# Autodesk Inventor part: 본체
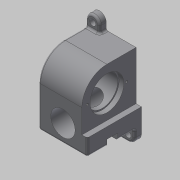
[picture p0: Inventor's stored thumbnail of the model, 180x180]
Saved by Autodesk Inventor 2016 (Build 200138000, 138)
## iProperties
Created: 2019-06
Part Number: 본체
Material: 일반
Document SubType Name: Modeling
Designer: mduedu
Density: 1 g/cm^3
Appearance: 기본값
Author: mduedu
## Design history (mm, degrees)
sketch "스케치1"
  geometry: L1 (37, 0)-(37, -43); L2 (37, -43)-(-60, -43); L3 (-60, -43)-(-60, 37); L4 (-60, 37)-(0, 37); A1 r 37 centre (0, 0) between (37, 0) and (0, 37); 1 further point
  constraints: 8 end point, 2 point on circle, 2 tangent, 1 centre point, 1 coincident, 1 horizontal, 1 parallel, 1 perpendicular, 1 vertical
  dimensions: "d0" = 37 radius of A1; "d2" = 80 distance of L2.end L3.end; "d3" = 97 distance of L1.end L2.end
extrude "돌출1" new body sketch "스케치1" stored distance "d4" = 72; taper "d5" = 0 deg
sketch "스케치2"
  geometry: L1 (72, 25)-(64, 25); L2 (64, 25)-(64, 97); L3 (64, 97)-(72, 97); L4 (72, 97)-(72, 25); L5 (72, 97)-(0, 97) reference; L6 (72, 60)-(72, 0) reference; 1 further point
  constraints: 8 end point, 2 collinear, 2 parallel, 1 horizontal, 1 perpendicular
  dimensions: "d6" = 72 distance between parallel lines of L1 L3; "d8" = 8 distance of L1.start L1.end
extrude "돌출2" cut sketch "스케치2" stored distance "d9" = 72; taper "d10" = 0 deg
sketch "스케치3"
  geometry: L1 (-36, -60)-(-36, 37) reference; L2 (-36, 37)-(28, 37) reference; L3 (28, 37)-(28, -35) reference; L4 (28, -35)-(36, -35) reference; L5 (36, -35)-(36, -60) reference; L6 (36, -60)-(-36, -60) reference; L7 (-36, 0)-(-19, 0); L8 (-19, 0)-(-19, 17.5); L9 (-19, 17.5)-(-36, 17.5); L10 (-36, 17.5)-(-36, 0); L11 (-19, 0)-(21, 0); L12 (21, 0)-(21, 23); L13 (21, 23)-(-19, 23); L14 (-19, 23)-(-19, 0); L15 (21, 0)-(28, 0); L16 (28, 0)-(28, 25); L17 (28, 25)-(21, 25); L18 (21, 25)-(21, 0); 1 further point
  constraints: 24 end point, 6 parallel, 3 horizontal, 3 perpendicular, 2 point on line, 1 horizontal alignment
  dimensions: "d11" = 7 distance of L16.end L17.end; "d13" = 47 distance between parallel lines of L3 L8; "d14" = 50 diameter of L17 L15; "d15" = 46 diameter of L13 L11; "d16" = 35 diameter of L9 L7
revolve "회전1" sketch "스케치3" stored, may be unused: angle "d17" = 90 deg
sketch "스케치4"
  geometry: C1 r 28 at (0, 0); 1 further point
  constraints: 1 centre point, 1 coincident
  dimensions: "d18" = 56 diameter of C1
extrude "돌출3" cut sketch "스케치4" distance "d19" = 2; taper "d20" = 0 deg
fillet "모깎기1" dims "d21" = 3
sketch "스케치5"
  geometry: C1 r 18 at (36, 26); 1 further point
  constraints: 1 centre point, 1 vertical alignment
  dimensions: "d22" = 36 diameter of C1; "d23" = 34 distance of C1.centre point (36, 60)
extrude "돌출4" cut sketch "스케치5" stored distance "d24" = 2; taper "d25" = 0 deg
sketch "스케치6"
  geometry: L1 (-37, -60)-(43, -60) reference; L2 (-8, -60)-(8, -60); L3 (8, -60)-(8, -51); L4 (8, -51)-(-8, -51); L5 (-8, -51)-(-8, -60); 2 further points
  constraints: 8 end point, 2 parallel, 1 horizontal, 1 midpoint, 1 perpendicular, 1 point on line, 1 vertical alignment
  dimensions: "d26" = 16 distance between parallel lines of L3 L5; "d28" = 9 distance between parallel lines of L1 L4
extrude "돌출5" cut sketch "스케치6" stored distance "d29" = 2; taper "d30" = 0 deg
sketch "스케치7"
  geometry: L1 (-10, -60)-(10, -60); L2 (10, -60)-(10, -48.967); L3 (10, -48.967)-(-10, -48.967); L4 (-10, -48.967)-(-10, -60); L5 (36, -60)-(-36, -60) reference; 3 further points
  constraints: 8 end point, 2 parallel, 1 collinear, 1 horizontal, 1 midpoint, 1 perpendicular, 1 vertical alignment, 2 other
  dimensions: "d31" = 20 distance of L2.end L3.end
extrude "돌출6" cut sketch "스케치7" stored distance "d33" = 2; taper "d34" = 0 deg
sketch "스케치8"
  geometry: L1 (0, 25)-(8, 25) reference; L2 (8, 25)-(8, 60) reference; L3 (72, 60)-(8, 60) reference; L4 (72, 0)-(72, 60) reference; L5 (72, 0)-(0, 0) reference; L6 (0, 25)-(0, 0) reference; L7 (72, 0)-(0, 0); L8 (0, 0)-(0, -20); L9 (0, -20)-(72, -20); L10 (72, -20)-(72, 0); C1 r 18 at (36, 26) reference; 1 further point
  constraints: 8 end point, 2 parallel, 1 horizontal, 1 perpendicular, 1 point on line
  dimensions: "d35" = 20 distance of L7.end L8.end
extrude "돌출7" join sketch "스케치8" distance "d37" = 10; taper "d38" = 0 deg
sketch "스케치9"
  geometry: L1 (0, -37)-(0, 0) reference; L2 (0, 0)-(64, 0) reference; L3 (64, -37)-(64, 0) reference; L4 (44, 0)-(64, 0); L5 (64, 0)-(64, 20); L6 (64, 20)-(44, 20); L7 (44, 20)-(44, 0); 1 further point
  constraints: 9 end point, 2 perpendicular, 1 horizontal, 1 parallel
  dimensions: "d39" = 20 distance of L2.end L5.end; "d51" = 20 distance of L5.end L6.end
extrude "돌출8" join sketch "스케치9" distance "d41" = 10; taper "d42" = 0 deg
fillet "모깎기2" dims "d43" = 10
sketch "스케치10"
  geometry: L1 (-62, -20)-(-10, -20) reference; L2 (0, -10)-(0, 0) reference; L3 (-72, 0)-(0, 0) reference; L4 (-72, 0)-(-72, -10) reference; C1 r 4.5 at (-62, -10); C2 r 4.5 at (-10, -10); A1 r 10 centre (-62, -10) between (-72, -10) and (-62, -20) reference; A2 r 10 centre (-10, -10) between (-10, -20) and (0, -10) reference; 1 further point
  constraints: 2 centre point, 2 coincident, 1 equal radius
  dimensions: "d44" = 9 diameter of C1
extrude "돌출9" cut sketch "스케치10" stored distance "d45" = 10; taper "d46" = 0 deg
sketch "스케치11"
  geometry: L1 (-64, 10)-(-64, 0) reference; L2 (-44, 0)-(-64, 0) reference; L3 (-44, 0)-(-44, 10) reference; C1 r 4.5 at (-54, 10); A1 r 10 centre (-54, 10) between (-44, 10) and (-64, 10) reference; 1 further point
  constraints: 1 centre point, 1 coincident
  dimensions: "d47" = 9 diameter of C1
extrude "돌출10" cut sketch "스케치11" stored distance "d48" = 10; taper "d49" = 0 deg
fillet "모깎기4" dims "d52" = 3
fillet "모깎기5" dims "d53" = 3
fillet "모깎기6" dims "d54" = 3
fillet "모깎기7" dims "d55" = 3
sketch "스케치12" dims "d56" = 58
  geometry: 3 further points
  constraints: 2 horizontal alignment, 1 coincident, 2 other
hole "구멍1" sketch "스케치12" at (66, 35) diameter "d57" = 3.242; stored, may be unused: countersink angle "d61" = 90 deg, drill point angle "d63" = 118 deg; dims "d58" = 10, "d59" = 4, "d60" = 2, "d62" = 12
sketch "스케치13" dims "d67" = 44
  geometry: 3 further points
  constraints: 2 vertical alignment, 1 coincident, 2 other
hole "구멍2" sketch "스케치13" at (0, 22) diameter "d68" = 3.242; stored, may be unused: countersink angle "d72" = 90 deg, drill point angle "d74" = 118 deg; dims "d69" = 10, "d70" = 4, "d71" = 2, "d73" = 12
sketch "스케치14"
  geometry: 3 further points
  constraints: 2 horizontal alignment
  dimensions: "d78" = 25 distance of point (11, 8) point (36, 8); "d79" = 25 distance of point (61, 8) point (36, 8)
hole "구멍3" sketch "스케치14" at (11, 8), (61, 8) diameter "d80" = 3.242; stored, may be unused: countersink angle "d84" = 90 deg, drill point angle "d86" = 118 deg; dims "d81" = 8, "d82" = 4, "d83" = 2, "d85" = 10
node "솔리드1"
pattern_circular "원형 패턴1" dims angle "d65" = 360 deg
pattern_circular "원형 패턴2" dims angle "d76" = 360 deg
node "투영된 루프1"
node "투영된 루프2"
node "투영된 루프3"
node "절단 모서리 투영1"
